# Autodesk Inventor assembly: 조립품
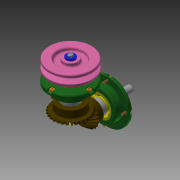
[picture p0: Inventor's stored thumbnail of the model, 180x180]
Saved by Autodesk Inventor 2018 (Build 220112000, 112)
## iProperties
Created: 2021-04
Part Number: 조립품
Material: 일반
Document SubType Name: Assembly
Designer: home
Author: home
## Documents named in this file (17)
- C:\Users\home\Desktop\710407V1015\조립품.iam
- C:\Users\home\Desktop\710407V1015\본체.ipt
- C:\Users\home\Desktop\710407V1015\커버.ipt
- C:\Users\home\Desktop\710407V1015\베어링 6203.ipt
- C:\Users\home\Desktop\710407V1015\오일실 17 x 32 x 8.ipt
- C:\Users\home\Desktop\710407V1015\메인 축.ipt
- 메인 축.ipt
- C:\Users\home\Desktop\710407V1015\서브 축.ipt
- 서브 축.ipt
- C:\Users\home\Desktop\710407V1015\메인 베벨기어.ipt
- C:\Users\home\Desktop\710407V1015\키 5 x 5 x 14.ipt
- C:\Users\home\Desktop\710407V1015\키 4 x 4 x 14.ipt
- C:\Users\home\Desktop\710407V1015\서브 베벨기어.ipt
- C:\Users\home\Desktop\710407V1015\V-벨트풀리.ipt
- C:\Users\home\Desktop\710407V1015\와셔 4 x 16.ipt
- C:\Users\home\Desktop\710407V1015\육각볼트 M4 x 8.ipt
- C:\Users\home\Desktop\710407V1015\볼트 M4 x 10.ipt
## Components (1 placed, 1 different names)
1. V-벨트풀리:1 — 각도:5
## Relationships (1: Angle 1)
- 각도:5 [Angle]: V-벨트풀리:1
